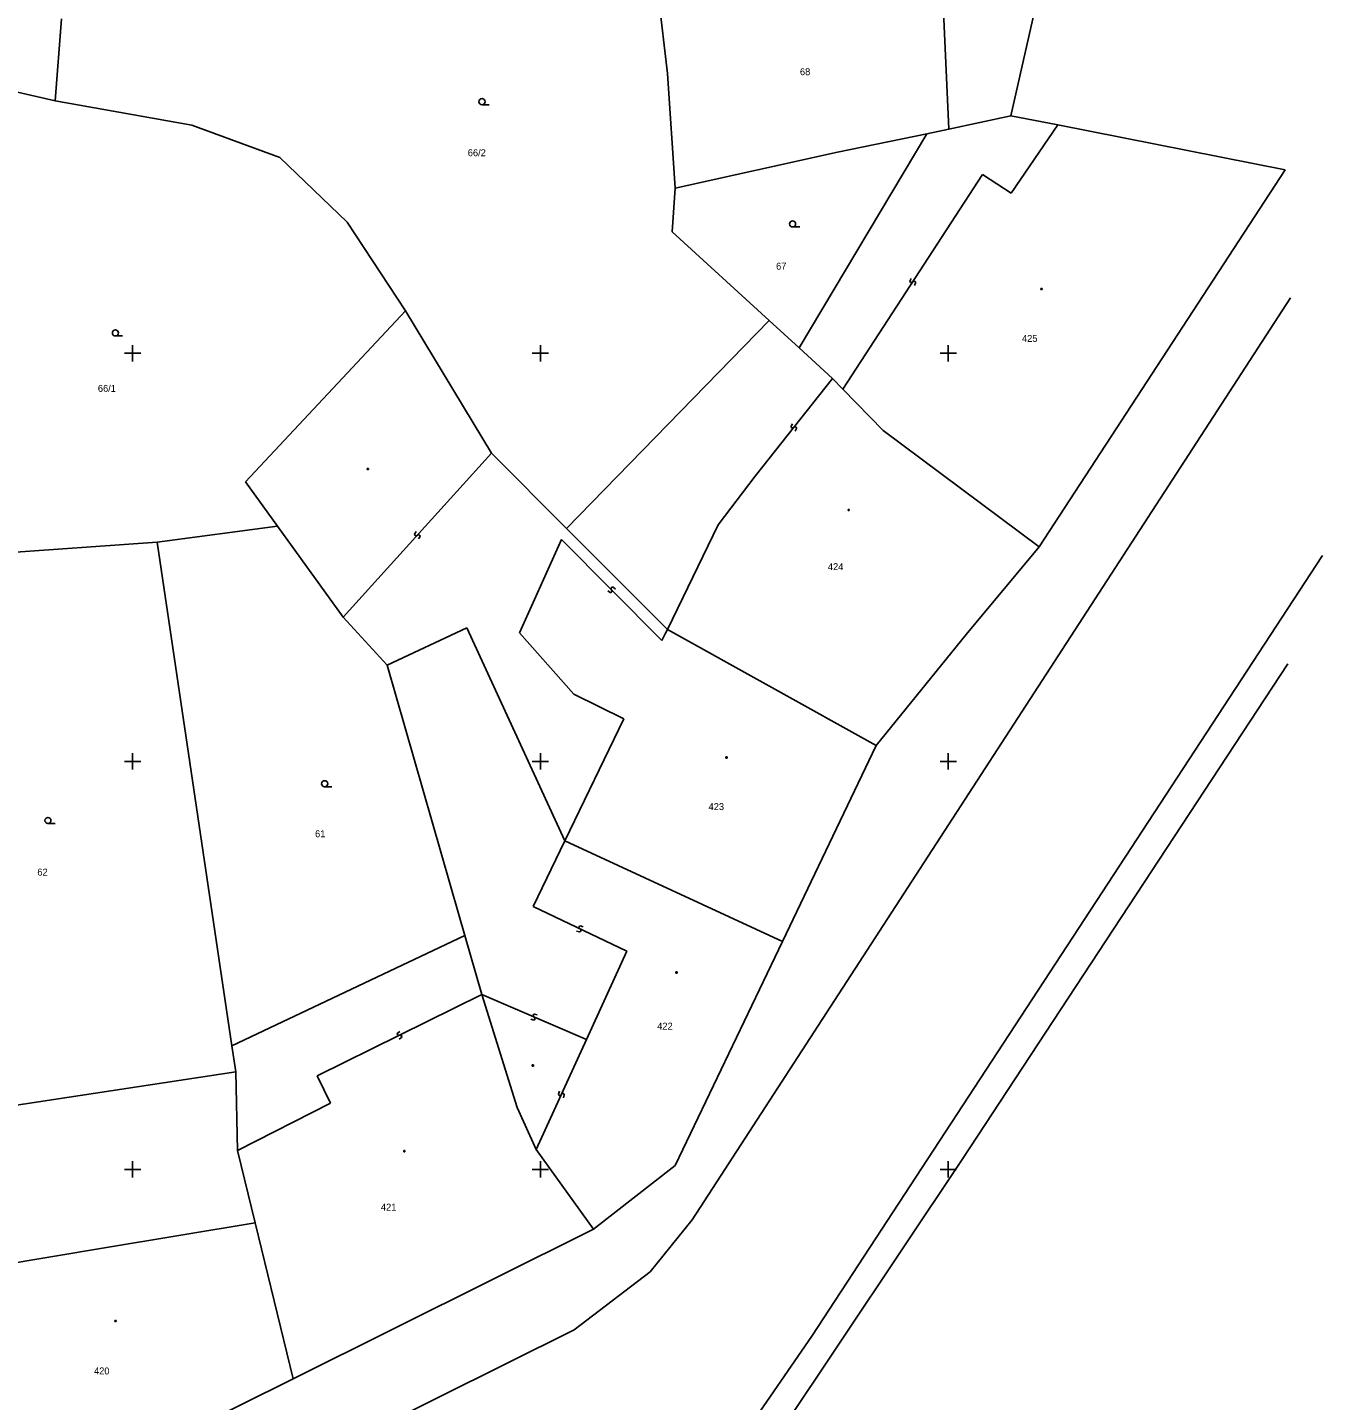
# Model space of a CAD drawing. Extents: x -492811 to -492366, y -1127107 to -1126748.
# Drawn here: x -492485.2 to -492421.6, y -1126911.3 to -1126844 of the extents above; entities that cross this region are included whole.
import ezdxf

# ---------------------------------------------------------------- set-up
doc = ezdxf.new("R2010")
doc.units = 0
doc.layers.add('katastrální mapa', color=7, linetype='Continuous')
doc.layers.add('síť', color=7, linetype='Continuous')

msp = doc.modelspace()

# ---------------------------------------------------------------- linework, layer by layer
at = {"layer": 'katastrální mapa'}
for p, q in [((-492440.52, -1126837.21), (-492439.96, -1126849.01)), ((-492436.93, -1126848.36), (-492434.78, -1126838.88)), ((-492454.5, -1126840.05), (-492453.76, -1126846.29)), ((-492483.79, -1126847.63), (-492483.49, -1126843.61)), ((-492453.76, -1126846.29), (-492453.39, -1126851.9)), ((-492485.85, -1126847.15), (-492483.79, -1126847.63)), ((-492483.79, -1126847.63), (-492477.09, -1126848.82)), ((-492462.86, -1126847.82), (-492462.51, -1126847.82)), ((-492439.96, -1126849.01), (-492436.93, -1126848.36)), ((-492436.93, -1126848.36), (-492434.62, -1126848.81)), ((-492477.09, -1126848.82), (-492472.77, -1126850.4)), ((-492447.3, -1126859.74), (-492441.04, -1126849.24)), ((-492445.43, -1126850.14), (-492441.04, -1126849.24)), ((-492441.04, -1126849.24), (-492439.96, -1126849.01)), ((-492436.91, -1126852.16), (-492434.62, -1126848.81)), ((-492434.62, -1126848.81), (-492423.48, -1126851.01)), ((-492472.77, -1126850.4), (-492469.48, -1126853.58)), ((-492453.39, -1126851.9), (-492445.43, -1126850.14)), ((-492445.16, -1126861.76), (-492438.32, -1126851.24)), ((-492438.32, -1126851.24), (-492436.91, -1126852.16)), ((-492435.54, -1126869.48), (-492423.48, -1126851.01)), ((-492453.53, -1126854.04), (-492453.39, -1126851.9)), ((-492469.48, -1126853.58), (-492466.61, -1126857.92)), ((-492453.53, -1126854.04), (-492448.78, -1126858.39)), ((-492447.63, -1126853.81), (-492447.28, -1126853.81)), ((-492441.82, -1126856.33), (-492441.88, -1126856.46)), ((-492441.88, -1126856.46), (-492441.87, -1126856.51)), ((-492441.87, -1126856.51), (-492441.83, -1126856.53)), ((-492441.83, -1126856.53), (-492441.78, -1126856.52)), ((-492441.78, -1126856.52), (-492441.7, -1126856.48)), ((-492441.7, -1126856.48), (-492441.65, -1126856.47)), ((-492441.6, -1126856.54), (-492441.66, -1126856.67)), ((-492441.65, -1126856.47), (-492441.61, -1126856.49)), ((-492441.61, -1126856.49), (-492441.6, -1126856.54)), ((-492423.21, -1126857.29), (-492452.56, -1126902.48)), ((-492435.45, -1126856.82), (-492435.39, -1126856.82)), ((-492435.45, -1126856.88), (-492435.45, -1126856.82)), ((-492435.39, -1126856.88), (-492435.45, -1126856.88)), ((-492435.39, -1126856.82), (-492435.39, -1126856.88)), ((-492474.46, -1126866.3), (-492466.61, -1126857.92)), ((-492466.61, -1126857.92), (-492462.4, -1126864.9)), ((-492458.72, -1126868.59), (-492448.78, -1126858.39)), ((-492448.78, -1126858.39), (-492447.3, -1126859.74)), ((-492480.84, -1126859.15), (-492480.49, -1126859.15)), ((-492447.3, -1126859.74), (-492445.68, -1126861.23)), ((-492449.46, -1126866.03), (-492445.68, -1126861.23)), ((-492445.68, -1126861.23), (-492445.16, -1126861.76)), ((-492445.16, -1126861.76), (-492443.19, -1126863.78)), ((-492447.63, -1126863.45), (-492447.7, -1126863.57)), ((-492447.7, -1126863.57), (-492447.7, -1126863.63)), ((-492447.7, -1126863.63), (-492447.67, -1126863.66)), ((-492447.67, -1126863.66), (-492447.61, -1126863.65)), ((-492447.61, -1126863.65), (-492447.53, -1126863.61)), ((-492447.53, -1126863.61), (-492447.47, -1126863.6)), ((-492447.44, -1126863.69), (-492447.51, -1126863.81)), ((-492447.47, -1126863.6), (-492447.44, -1126863.63)), ((-492447.44, -1126863.63), (-492447.44, -1126863.69)), ((-492443.19, -1126863.78), (-492435.54, -1126869.48)), ((-492469.67, -1126872.94), (-492462.4, -1126864.9)), ((-492462.4, -1126864.9), (-492458.72, -1126868.59)), ((-492468.49, -1126865.64), (-492468.43, -1126865.64)), ((-492468.49, -1126865.7), (-492468.49, -1126865.64)), ((-492468.43, -1126865.7), (-492468.49, -1126865.7)), ((-492468.43, -1126865.64), (-492468.43, -1126865.7)), ((-492451.28, -1126868.41), (-492449.46, -1126866.03)), ((-492474.46, -1126866.3), (-492472.89, -1126868.48)), ((-492444.91, -1126867.65), (-492444.85, -1126867.65)), ((-492444.91, -1126867.71), (-492444.91, -1126867.65)), ((-492444.85, -1126867.71), (-492444.91, -1126867.71)), ((-492444.85, -1126867.65), (-492444.85, -1126867.71)), ((-492478.79, -1126869.25), (-492472.89, -1126868.48)), ((-492472.89, -1126868.48), (-492469.67, -1126872.94)), ((-492466.09, -1126868.74), (-492466.17, -1126868.86)), ((-492458.72, -1126868.59), (-492453.77, -1126873.54)), ((-492453.77, -1126873.54), (-492451.28, -1126868.41)), ((-492492.39, -1126870.23), (-492478.79, -1126869.25)), ((-492478.79, -1126869.25), (-492475.13, -1126893.94)), ((-492466.17, -1126868.86), (-492466.16, -1126868.91)), ((-492466.16, -1126868.91), (-492466.13, -1126868.94)), ((-492466.13, -1126868.94), (-492466.08, -1126868.94)), ((-492466.08, -1126868.94), (-492465.99, -1126868.9)), ((-492465.99, -1126868.9), (-492465.94, -1126868.9)), ((-492465.9, -1126868.98), (-492465.98, -1126869.1)), ((-492465.94, -1126868.9), (-492465.91, -1126868.93)), ((-492465.91, -1126868.93), (-492465.9, -1126868.98)), ((-492461.02, -1126873.7), (-492458.97, -1126869.12)), ((-492458.97, -1126869.12), (-492454.04, -1126874.08)), ((-492439.11, -1126873.79), (-492435.54, -1126869.48)), ((-492421.64, -1126869.91), (-492446.69, -1126908.18)), ((-492456.49, -1126871.47), (-492456.52, -1126871.5)), ((-492456.52, -1126871.5), (-492456.52, -1126871.56)), ((-492456.43, -1126871.47), (-492456.49, -1126871.47)), ((-492456.32, -1126871.56), (-492456.43, -1126871.47)), ((-492456.58, -1126871.73), (-492456.69, -1126871.64)), ((-492456.52, -1126871.73), (-492456.58, -1126871.73)), ((-492456.52, -1126871.56), (-492456.49, -1126871.64)), ((-492456.49, -1126871.7), (-492456.52, -1126871.73)), ((-492456.49, -1126871.64), (-492456.49, -1126871.7)), ((-492469.67, -1126872.94), (-492467.52, -1126875.28)), ((-492467.52, -1126875.28), (-492463.61, -1126873.45)), ((-492463.61, -1126873.45), (-492458.8, -1126883.9)), ((-492453.86, -1126873.71), (-492453.77, -1126873.54)), ((-492453.77, -1126873.54), (-492443.53, -1126879.23)), ((-492458.36, -1126876.7), (-492461.02, -1126873.7)), ((-492454.04, -1126874.08), (-492453.86, -1126873.71)), ((-492443.53, -1126879.23), (-492439.11, -1126873.79)), ((-492467.52, -1126875.28), (-492463.98, -1126887.58)), ((-492439.32, -1126899.52), (-492423.34, -1126875.22)), ((-492455.9, -1126877.91), (-492458.36, -1126876.7)), ((-492458.8, -1126883.9), (-492455.9, -1126877.91)), ((-492448.13, -1126888.83), (-492443.53, -1126879.23)), ((-492450.9, -1126879.78), (-492450.84, -1126879.78)), ((-492450.9, -1126879.84), (-492450.9, -1126879.78)), ((-492450.84, -1126879.84), (-492450.9, -1126879.84)), ((-492450.84, -1126879.78), (-492450.84, -1126879.84)), ((-492470.58, -1126881.25), (-492470.23, -1126881.25)), ((-492484.15, -1126883.05), (-492483.8, -1126883.05)), ((-492460.36, -1126887.12), (-492458.8, -1126883.9)), ((-492458.8, -1126883.9), (-492448.13, -1126888.83)), ((-492463.98, -1126887.58), (-492463.7, -1126888.54)), ((-492460.36, -1126887.12), (-492455.76, -1126889.31)), ((-492458.08, -1126888.36), (-492458.22, -1126888.32)), ((-492458.09, -1126888.09), (-492458.11, -1126888.13)), ((-492458.11, -1126888.13), (-492458.09, -1126888.18)), ((-492458.04, -1126888.07), (-492458.09, -1126888.09)), ((-492458.09, -1126888.18), (-492458.03, -1126888.25)), ((-492458.03, -1126888.34), (-492458.08, -1126888.36)), ((-492457.9, -1126888.11), (-492458.04, -1126888.07)), ((-492458.03, -1126888.25), (-492458.01, -1126888.3)), ((-492458.01, -1126888.3), (-492458.03, -1126888.34)), ((-492475.13, -1126893.94), (-492463.7, -1126888.54)), ((-492463.7, -1126888.54), (-492462.87, -1126891.43)), ((-492453.39, -1126899.81), (-492448.13, -1126888.83)), ((-492457.74, -1126893.64), (-492455.76, -1126889.31)), ((-492453.35, -1126890.32), (-492453.29, -1126890.32)), ((-492453.35, -1126890.38), (-492453.35, -1126890.32)), ((-492453.29, -1126890.38), (-492453.35, -1126890.38)), ((-492453.29, -1126890.32), (-492453.29, -1126890.38)), ((-492470.95, -1126895.42), (-492462.87, -1126891.43)), ((-492462.87, -1126891.43), (-492457.74, -1126893.64)), ((-492462.87, -1126891.43), (-492461.13, -1126896.96)), ((-492460.29, -1126892.39), (-492460.34, -1126892.41)), ((-492460.15, -1126892.43), (-492460.29, -1126892.39)), ((-492460.32, -1126892.68), (-492460.46, -1126892.64)), ((-492460.34, -1126892.41), (-492460.35, -1126892.45)), ((-492460.35, -1126892.45), (-492460.33, -1126892.5)), ((-492460.33, -1126892.5), (-492460.28, -1126892.57)), ((-492460.27, -1126892.66), (-492460.32, -1126892.68)), ((-492460.28, -1126892.57), (-492460.26, -1126892.62)), ((-492460.26, -1126892.62), (-492460.27, -1126892.66)), ((-492467.01, -1126893.32), (-492467.03, -1126893.37)), ((-492467.03, -1126893.37), (-492467.01, -1126893.41)), ((-492466.89, -1126893.24), (-492467.01, -1126893.32)), ((-492467.01, -1126893.41), (-492466.95, -1126893.42)), ((-492466.95, -1126893.42), (-492466.87, -1126893.43)), ((-492466.81, -1126893.53), (-492466.93, -1126893.61)), ((-492466.87, -1126893.43), (-492466.81, -1126893.44)), ((-492466.81, -1126893.44), (-492466.79, -1126893.48)), ((-492466.79, -1126893.48), (-492466.81, -1126893.53)), ((-492460.2, -1126899.02), (-492457.74, -1126893.64)), ((-492475.13, -1126893.94), (-492474.93, -1126895.22)), ((-492460.4, -1126894.88), (-492460.34, -1126894.88)), ((-492460.4, -1126894.94), (-492460.4, -1126894.88)), ((-492460.34, -1126894.94), (-492460.4, -1126894.94)), ((-492460.34, -1126894.88), (-492460.34, -1126894.94)), ((-492490.71, -1126897.61), (-492474.93, -1126895.22)), ((-492474.93, -1126895.22), (-492474.85, -1126899.08)), ((-492470.95, -1126895.42), (-492470.29, -1126896.76)), ((-492459.07, -1126896.17), (-492459.11, -1126896.31)), ((-492459.11, -1126896.31), (-492459.09, -1126896.36)), ((-492459.09, -1126896.36), (-492459.06, -1126896.38)), ((-492459.06, -1126896.38), (-492459, -1126896.36)), ((-492459, -1126896.36), (-492458.94, -1126896.3)), ((-492458.94, -1126896.3), (-492458.88, -1126896.28)), ((-492458.88, -1126896.28), (-492458.85, -1126896.3)), ((-492458.83, -1126896.35), (-492458.87, -1126896.49)), ((-492458.85, -1126896.3), (-492458.83, -1126896.35)), ((-492474.85, -1126899.08), (-492470.29, -1126896.76)), ((-492461.13, -1126896.96), (-492460.2, -1126899.02)), ((-492474.85, -1126899.08), (-492473.99, -1126902.62)), ((-492466.7, -1126899.08), (-492466.64, -1126899.08)), ((-492466.7, -1126899.14), (-492466.7, -1126899.08)), ((-492466.64, -1126899.08), (-492466.64, -1126899.14)), ((-492460.2, -1126899.02), (-492457.4, -1126902.93)), ((-492466.64, -1126899.14), (-492466.7, -1126899.14)), ((-492457.4, -1126902.93), (-492453.39, -1126899.81)), ((-492457.09, -1126926.08), (-492439.32, -1126899.52)), ((-492452.56, -1126902.48), (-492454.61, -1126905.02)), ((-492481.38, -1126903.85), (-492473.99, -1126902.62)), ((-492473.99, -1126902.62), (-492472.13, -1126910.26)), ((-492472.13, -1126910.26), (-492457.4, -1126902.93)), ((-492489.93, -1126905.27), (-492481.38, -1126903.85)), ((-492458.35, -1126907.86), (-492454.61, -1126905.02)), ((-492458.35, -1126907.86), (-492531.1, -1126944.05)), ((-492480.87, -1126907.4), (-492480.81, -1126907.4)), ((-492480.87, -1126907.46), (-492480.87, -1126907.4)), ((-492480.81, -1126907.46), (-492480.87, -1126907.46)), ((-492480.81, -1126907.4), (-492480.81, -1126907.46)), ((-492446.69, -1126908.18), (-492453.01, -1126917.31)), ((-492487.04, -1126917.67), (-492472.13, -1126910.26))]:
    msp.add_line(p, q, dxfattribs=at)
for centre in [(-492462.86, -1126847.67), (-492447.63, -1126853.66), (-492480.84, -1126859), (-492470.58, -1126881.1), (-492484.15, -1126882.9)]:
    msp.add_circle(centre, 0.15, dxfattribs=at)
at = {"layer": 'síť'}
for p, q in [((-492480.4, -1126860), (-492479.6, -1126860)), ((-492480, -1126859.6), (-492480, -1126860.4)), ((-492460.4, -1126860), (-492459.6, -1126860)), ((-492460, -1126859.6), (-492460, -1126860.4)), ((-492440.4, -1126860), (-492439.6, -1126860)), ((-492440, -1126859.6), (-492440, -1126860.4)), ((-492480, -1126879.6), (-492480, -1126880.4)), ((-492460, -1126879.6), (-492460, -1126880.4)), ((-492440, -1126879.6), (-492440, -1126880.4)), ((-492480.4, -1126880), (-492479.6, -1126880)), ((-492460.4, -1126880), (-492459.6, -1126880)), ((-492440.4, -1126880), (-492439.6, -1126880)), ((-492480, -1126899.6), (-492480, -1126900.4)), ((-492460, -1126899.6), (-492460, -1126900.4)), ((-492440, -1126899.6), (-492440, -1126900.4)), ((-492480.4, -1126900), (-492479.6, -1126900)), ((-492460.4, -1126900), (-492459.6, -1126900)), ((-492440.4, -1126900), (-492439.6, -1126900))]:
    msp.add_line(p, q, dxfattribs=at)

# ---------------------------------------------------------------- texts
at = {"layer": 'katastrální mapa'}
for s, p in [('68', (-492447.27, -1126846.37)), ('66/2', (-492463.56, -1126850.34)), ('67', (-492448.44, -1126855.9)), ('425', (-492436.38, -1126859.44)), ('66/1', (-492481.7, -1126861.89)), ('424', (-492445.9, -1126870.63)), ('423', (-492451.75, -1126882.39)), ('61', (-492471.05, -1126883.72)), ('62', (-492484.67, -1126885.6)), ('422', (-492454.27, -1126893.15)), ('421', (-492467.82, -1126902.02)), ('420', (-492481.89, -1126910.05))]:
    msp.add_text(s, height=0.34, dxfattribs=at).set_placement(p)

doc.saveas('drawing.dxf')
